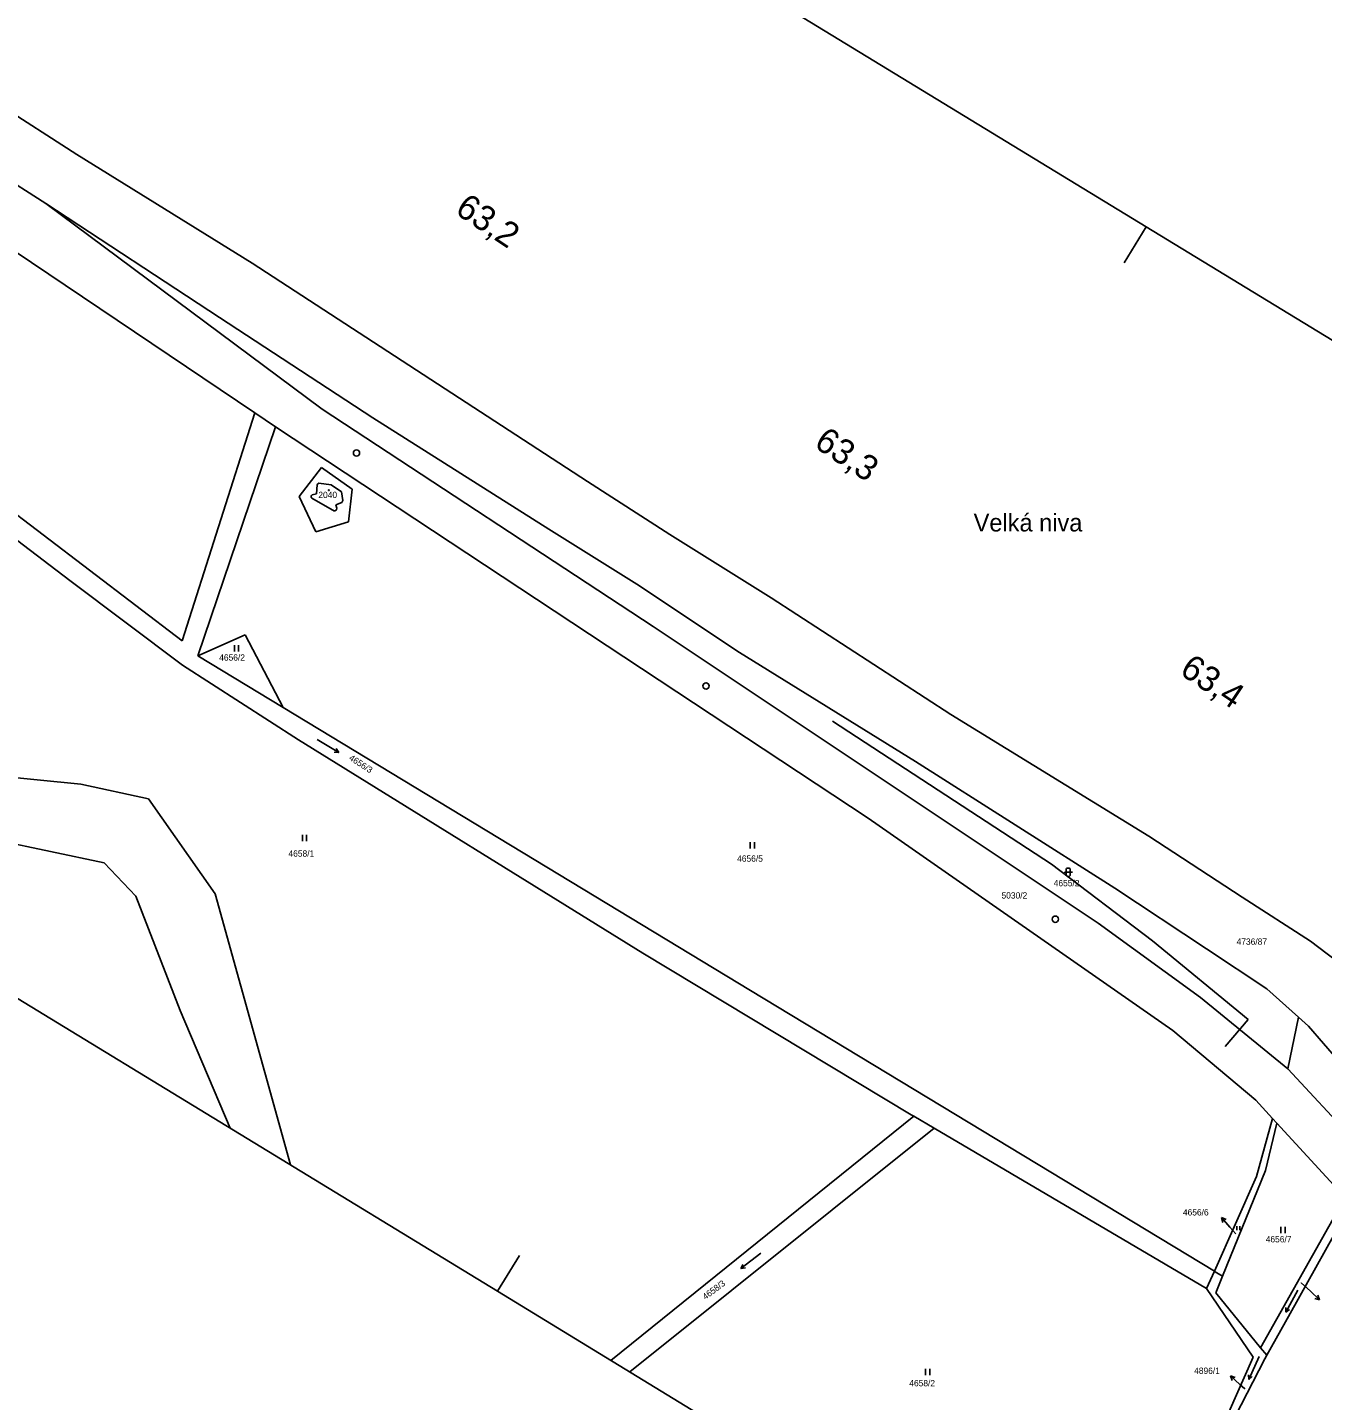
# Model space of a CAD drawing. Extents: x -804899 to -803847, y -1165742 to -1164942.
# Drawn here: x -804472.7 to -804164, y -1165549.5 to -1165222.3 of the extents above; entities that cross this region are included whole.
import ezdxf

# ---------------------------------------------------------------- set-up
doc = ezdxf.new("R2010")
doc.units = 0
for name, color, linetype in [('Default', 7, 'Continuous'), ('formát', 7, 'Continuous'), ('kilometráž - vrstava 7', 7, 'Continuous'), ('kn_celek - Cisla parcel pomocna', 7, 'Continuous'), ('kn_celek - Cisla pozemkovych parcel', 7, 'Continuous'), ('kn_celek - Cisla stavebnich parcel', 7, 'Continuous'), ('kn_celek - Dalsi prvky mapy popis', 7, 'Continuous'), ('kn_celek - Hranice parcel', 7, 'Continuous'), ('kn_celek - Vnitrni kresby', 7, 'Continuous'), ('kn_celek - Znacky budov', 7, 'Continuous'), ('kn_celek - Znacky kultur', 7, 'Continuous'), ('plochy - SZDC', 7, 'Continuous'), ('PSR_C2_3_trasa_Lenora - Kabelová trasa', 7, 'Continuous')]:
    doc.layers.add(name, color=color, linetype=linetype)

# ---------------------------------------------------------------- blocks, each defined once
blk = doc.blocks.new('316')
at = {"layer": 'Default'}
for p, q in [((-8.3, 10), (-10, 8.1)), ((-5, 10), (-8.3, 10)), ((-5, 15.5), (-5, 4.5)), ((-5, 10), (5, 10)), ((0.5, 20), (-0.5, 20)), ((-0.5, 0), (0.5, 0)), ((5, 4.5), (5, 15.5)), ((10, 10), (5, 10))]:
    blk.add_line(p, q, dxfattribs=at)
for centre, start, end in [((-0.5, 15.5), 90, 180), ((-0.5, 4.5), 180, 270), ((0.5, 15.5), 0, 90), ((0.5, 4.5), 270, 0)]:
    blk.add_arc(centre, 4.5, start, end, dxfattribs=at)
blk = doc.blocks.new('306')
at = {"layer": 'Default'}
for p, q in [((-5.2, 0), (-5.2, 15)), ((4.8, 0), (4.8, 15))]:
    blk.add_line(p, q, dxfattribs=at)
blk = doc.blocks.new('802')
at = {"layer": 'Default'}
for p, q in [((-30, 0), (30, 0)), ((20, 5), (30, 0)), ((30, 0), (20, -5))]:
    blk.add_line(p, q, dxfattribs=at)
blk = doc.blocks.new('402')
at = {"layer": 'Default'}
for p, q in [((-0.8, 0.8), (0.7, 0.8)), ((-0.8, 0.8), (-0.8, -0.7)), ((0.7, 0.8), (0.7, -0.7)), ((0.7, -0.7), (-0.8, -0.7))]:
    blk.add_line(p, q, dxfattribs=at)
blk = doc.blocks.new('Z61')
at = {"layer": 'Default'}
for p, q in [((0, 0), (30, 0)), ((30, 0), (19.2, 5.3)), ((30, 0), (19.2, -5.3))]:
    blk.add_line(p, q, dxfattribs=at)

msp = doc.modelspace()

# ---------------------------------------------------------------- linework, layer by layer
at = {"layer": 'formát'}
for p, q in [((-804206.05, -1165269.84), (-804743.98, -1164941.92)), ((-804360.64, -1165523.44), (-804898.57, -1165195.52)), ((-804206.05, -1165269.84), (-804211.25, -1165278.38)), ((-804026.74, -1165379.15), (-804206.05, -1165269.84)), ((-804355.43, -1165514.9), (-804360.64, -1165523.44)), ((-804181.33, -1165632.74), (-804360.64, -1165523.44))]:
    msp.add_line(p, q, dxfattribs=at)
at = {"layer": 'kilometráž - vrstava 7'}
for centre in [(-804394.24, -1165323.73), (-804310.94, -1165379.23), (-804227.7, -1165434.8)]:
    msp.add_circle(centre, 0.75, dxfattribs=at)
at = {"layer": 'kn_celek - Cisla parcel pomocna'}
for p, q in [((-804184.66, -1165509.79), (-804186.1, -1165508.15)), ((-804169.08, -1165521.47), (-804166.91, -1165523.46)), ((-804182.56, -1165546.73), (-804183.74, -1165545.65))]:
    msp.add_line(p, q, dxfattribs=at)
at = {"layer": 'kn_celek - Hranice parcel'}
for p, q in [((-804512.48, -1165219.51), (-804460.87, -1165252.62)), ((-804552.85, -1165223.84), (-804418.46, -1165314.18)), ((-804519.76, -1165231.32), (-804468.27, -1165264.32)), ((-804611.48, -1165241.21), (-804462.54, -1165354.11)), ((-804460.87, -1165252.62), (-804419.13, -1165278.5)), ((-804579.26, -1165259.3), (-804435.81, -1165368.47)), ((-804468.27, -1165264.32), (-804402.46, -1165313.29)), ((-804468.27, -1165264.32), (-804426.86, -1165291.43)), ((-804419.13, -1165278.5), (-804339.16, -1165330.48)), ((-804426.86, -1165291.43), (-804390.35, -1165315.35)), ((-804435.81, -1165368.47), (-804418.46, -1165314.18)), ((-804418.46, -1165314.18), (-804413.53, -1165317.49)), ((-804402.46, -1165313.29), (-804323.51, -1165365.07)), ((-804413.53, -1165317.49), (-804432.07, -1165372.08)), ((-804413.53, -1165317.49), (-804272.3, -1165410.7)), ((-804390.35, -1165315.35), (-804348.41, -1165341.86)), ((-804402.61, -1165327.22), (-804407.87, -1165334.06)), ((-804395.25, -1165332.31), (-804402.61, -1165327.22)), ((-804339.16, -1165330.48), (-804319.55, -1165343.18)), ((-804396.17, -1165340.16), (-804395.25, -1165332.31)), ((-804407.87, -1165334.06), (-804403.92, -1165342.5)), ((-804403.92, -1165342.5), (-804396.17, -1165340.16)), ((-804348.41, -1165341.86), (-804327.45, -1165354.94)), ((-804319.55, -1165343.18), (-804295.39, -1165358.24)), ((-804462.54, -1165354.11), (-804435.75, -1165374.24)), ((-804327.45, -1165354.94), (-804302.94, -1165371.26)), ((-804295.39, -1165358.24), (-804252.61, -1165386.06)), ((-804323.51, -1165365.07), (-804217.51, -1165435.77)), ((-804432.07, -1165372.08), (-804420.77, -1165367.05)), ((-804420.77, -1165367.05), (-804411.74, -1165384.38)), ((-804432.07, -1165372.08), (-804411.74, -1165384.38)), ((-804302.94, -1165371.26), (-804261.01, -1165397.26)), ((-804435.75, -1165374.24), (-804408.07, -1165392.08)), ((-804411.74, -1165384.38), (-804300.34, -1165451.78)), ((-804252.61, -1165386.06), (-804205.41, -1165415.05)), ((-804408.07, -1165392.08), (-804326.03, -1165442.88)), ((-804509.08, -1165397.79), (-804459.92, -1165402.62)), ((-804213.5, -1165427.44), (-804261.01, -1165397.26)), ((-804459.92, -1165402.62), (-804443.8, -1165406.13)), ((-804443.8, -1165406.13), (-804427.89, -1165428.73)), ((-804199.72, -1165461.33), (-804272.3, -1165410.7)), ((-804489.41, -1165414.02), (-804454.38, -1165421.34)), ((-804205.41, -1165415.05), (-804183.17, -1165429.52)), ((-804454.38, -1165421.34), (-804446.86, -1165429.35)), ((-804427.89, -1165428.73), (-804410, -1165493.35)), ((-804191.69, -1165441.88), (-804213.5, -1165427.44)), ((-804446.86, -1165429.35), (-804436.25, -1165456.55)), ((-804183.17, -1165429.52), (-804166.9, -1165440.05)), ((-804217.51, -1165435.77), (-804193.11, -1165453.43)), ((-804177.28, -1165451.4), (-804191.69, -1165441.88)), ((-804166.9, -1165440.05), (-804154.41, -1165449.48)), ((-804326.03, -1165442.88), (-804262.02, -1165481.4)), ((-804300.34, -1165451.78), (-804189.78, -1165518.67)), ((-804169.73, -1165458.18), (-804177.28, -1165451.4)), ((-804193.11, -1165453.43), (-804172.29, -1165470.42)), ((-804436.25, -1165456.55), (-804424.34, -1165484.6)), ((-804172.29, -1165470.42), (-804169.73, -1165458.18)), ((-804167.35, -1165460.31), (-804169.73, -1165458.18)), ((-804179.93, -1165477.89), (-804199.72, -1165461.33)), ((-804156, -1165473.46), (-804167.35, -1165460.31)), ((-804172.29, -1165470.42), (-804129.3, -1165516.81)), ((-804179.93, -1165477.89), (-804175.89, -1165482.28)), ((-804261.39, -1165481.77), (-804333.6, -1165539.92)), ((-804261.39, -1165481.77), (-804262.02, -1165481.4)), ((-804256.6, -1165484.59), (-804261.39, -1165481.77)), ((-804179.73, -1165496.08), (-804175.89, -1165482.28)), ((-804174.86, -1165483.4), (-804177.56, -1165494.7)), ((-804175.89, -1165482.28), (-804174.86, -1165483.4)), ((-804174.86, -1165483.4), (-804158.61, -1165501.07)), ((-804256.6, -1165484.59), (-804329.11, -1165542.66)), ((-804191.62, -1165522.81), (-804256.6, -1165484.59)), ((-804189.78, -1165518.67), (-804179.73, -1165496.08)), ((-804177.56, -1165494.7), (-804187.83, -1165519.85)), ((-804178.76, -1165536.91), (-804158.61, -1165501.07)), ((-804171.74, -1165528.78), (-804157.17, -1165502.7)), ((-804191.62, -1165522.81), (-804189.78, -1165518.67)), ((-804189.78, -1165518.67), (-804189.59, -1165518.78)), ((-804189.59, -1165518.78), (-804187.83, -1165519.85)), ((-804187.83, -1165519.85), (-804189.46, -1165523.84)), ((-804191.62, -1165522.81), (-804180.56, -1165539.16)), ((-804189.46, -1165523.84), (-804178.76, -1165536.91)), ((-804177.29, -1165538.71), (-804171.74, -1165528.78)), ((-804180.56, -1165539.16), (-804186.32, -1165552.24)), ((-804184.8, -1165553.3), (-804177.76, -1165539.56)), ((-804178.76, -1165536.91), (-804177.29, -1165538.71)), ((-804177.76, -1165539.56), (-804177.29, -1165538.71))]:
    msp.add_line(p, q, dxfattribs=at)
at = {"layer": 'kn_celek - Vnitrni kresby'}
for p, q in [((-804405.03, -1165334.04), (-804404.95, -1165333.84)), ((-804405.03, -1165334.34), (-804405.03, -1165334.04)), ((-804404.95, -1165333.84), (-804404.81, -1165333.67)), ((-804404.81, -1165333.67), (-804403.75, -1165333.45)), ((-804403.75, -1165333.45), (-804403.61, -1165331.31)), ((-804403.61, -1165331.31), (-804403.46, -1165331.1)), ((-804403.46, -1165331.1), (-804403.19, -1165330.9)), ((-804403.19, -1165330.9), (-804400.24, -1165331.34)), ((-804400.24, -1165331.34), (-804397.82, -1165332.97)), ((-804397.82, -1165332.97), (-804397.53, -1165335.03)), ((-804404.89, -1165334.45), (-804405.03, -1165334.34)), ((-804399.5, -1165337.55), (-804404.89, -1165334.45)), ((-804397.75, -1165335.5), (-804399.17, -1165336.08)), ((-804399.17, -1165336.08), (-804398.9, -1165336.87)), ((-804399.01, -1165337.18), (-804399.09, -1165337.37)), ((-804398.9, -1165336.87), (-804399.01, -1165337.18)), ((-804397.54, -1165335.23), (-804397.75, -1165335.5)), ((-804397.53, -1165335.03), (-804397.54, -1165335.23)), ((-804399.4, -1165337.54), (-804399.5, -1165337.55)), ((-804399.09, -1165337.37), (-804399.4, -1165337.54))]:
    msp.add_line(p, q, dxfattribs=at)
at = {"layer": 'plochy - SZDC'}
for p, q in [((-804552.85, -1165223.84), (-804418.46, -1165314.18)), ((-804468.27, -1165264.32), (-804519.76, -1165231.32)), ((-804426.86, -1165291.43), (-804468.27, -1165264.32)), ((-804468.27, -1165264.32), (-804402.46, -1165313.29)), ((-804402.46, -1165313.29), (-804468.27, -1165264.32)), ((-804390.35, -1165315.35), (-804426.86, -1165291.43)), ((-804418.46, -1165314.18), (-804413.53, -1165317.49)), ((-804402.46, -1165313.29), (-804323.51, -1165365.07)), ((-804323.51, -1165365.07), (-804402.46, -1165313.29)), ((-804413.53, -1165317.49), (-804272.3, -1165410.7)), ((-804348.41, -1165341.86), (-804390.35, -1165315.35)), ((-804327.45, -1165354.94), (-804348.41, -1165341.86)), ((-804302.94, -1165371.26), (-804327.45, -1165354.94)), ((-804323.51, -1165365.07), (-804217.51, -1165435.77)), ((-804217.51, -1165435.77), (-804323.51, -1165365.07)), ((-804261.01, -1165397.26), (-804302.94, -1165371.26)), ((-804213.5, -1165427.44), (-804261.01, -1165397.26)), ((-804272.3, -1165410.7), (-804199.72, -1165461.33)), ((-804191.69, -1165441.88), (-804213.5, -1165427.44)), ((-804217.51, -1165435.77), (-804193.11, -1165453.43)), ((-804193.11, -1165453.43), (-804217.51, -1165435.77)), ((-804177.28, -1165451.4), (-804191.69, -1165441.88)), ((-804169.73, -1165458.18), (-804177.28, -1165451.4)), ((-804193.11, -1165453.43), (-804172.29, -1165470.42)), ((-804172.29, -1165470.42), (-804193.11, -1165453.43)), ((-804172.29, -1165470.42), (-804169.73, -1165458.18)), ((-804199.72, -1165461.33), (-804179.93, -1165477.89)), ((-804129.3, -1165516.81), (-804172.29, -1165470.42)), ((-804179.93, -1165477.89), (-804175.89, -1165482.28)), ((-804175.89, -1165482.28), (-804174.86, -1165483.4)), ((-804174.86, -1165483.4), (-804158.61, -1165501.07))]:
    msp.add_line(p, q, dxfattribs=at)
at = {"layer": 'PSR_C2_3_trasa_Lenora - Kabelová trasa'}
msp.add_line((-804181.72, -1165458.66), (-804187.21, -1165465.17), dxfattribs=at)
msp.add_lwpolyline([(-804280.78, -1165387.58), (-804228.57, -1165421.69), (-804204.49, -1165439.97), (-804181.72, -1165458.66)], dxfattribs=at)

# ---------------------------------------------------------------- block references
at = {"layer": 'kn_celek - Cisla parcel pomocna', "xscale": 0.1, "yscale": 0.10000000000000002}
for p, rotation in [((-804186.1, -1165508.15), 131.16510000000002), ((-804166.91, -1165523.46), -42.54615000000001), ((-804183.74, -1165545.65), 137.64257999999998)]:
    msp.add_blockref('Z61', p, dxfattribs=dict(at, rotation=rotation))
at = {"layer": 'kn_celek - Znacky budov', "xscale": 0.1, "yscale": 0.10000000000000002}
msp.add_blockref('402', (-804400.86, -1165332.56), dxfattribs=at)
at = {"layer": 'kn_celek - Znacky kultur'}
for name, p, xscale, yscale in [('306', (-804422.82, -1165370.99), 0.1, 0.10000000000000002), ('306', (-804406.62, -1165416.24), 0.1, 0.10000000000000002), ('306', (-804299.86, -1165417.93), 0.1, 0.10000000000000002), ('316', (-804224.62, -1165424.63), 0.1, 0.10000000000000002), ('306', (-804184.05, -1165508.93), 0.067, 0.067), ('306', (-804173.4, -1165509.61), 0.1, 0.10000000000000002), ('306', (-804258.11, -1165543.41), 0.1, 0.10000000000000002)]:
    msp.add_blockref(name, p, dxfattribs=dict(at, xscale=xscale, yscale=yscale))
for p, xscale, yscale, rotation in [((-804401.03, -1165393.52), 0.1, 0.10000000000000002, -31.53986999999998), ((-804300.28, -1165516.23), 0.1, 0.09999999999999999, -142.49439), ((-804171.33, -1165525.83), 0.10000000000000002, 0.1, -118.66841999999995), ((-804180.37, -1165541.74), 0.10000000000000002, 0.1, -114.27461999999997)]:
    msp.add_blockref('802', p, dxfattribs=dict(at, xscale=xscale, yscale=yscale, rotation=rotation))

# ---------------------------------------------------------------- texts
at = {"layer": 'kilometráž - vrstava 7'}
for s, rotation, p in [('63,2', 326.3093, (-804371.02, -1165266.51)), ('63,3', 326.3024, (-804285.46, -1165322.14)), ('63,4', 326.2162, (-804198.33, -1165376.26))]:
    msp.add_text(s, height=6, rotation=rotation, dxfattribs=at).set_placement(p)
at = {"layer": 'kn_celek - Cisla parcel pomocna'}
for s, p in [('4656/6', (-804197.28, -1165505.39)), ('4896/1', (-804194.6, -1165543.13))]:
    msp.add_text(s, height=1.5, dxfattribs=at).set_placement(p)
at = {"layer": 'kn_celek - Cisla pozemkovych parcel'}
for s, height, p in [('4656/2', 1.5, (-804426.96, -1165373.19)), ('4658/1', 1.5, (-804410.45, -1165419.9)), ('4656/5', 1.5, (-804303.52, -1165421.1)), ('4655/2', 1.5, (-804228.07, -1165426.95)), ('5030/2', 1.5, (-804240.51, -1165429.88)), ('4736/87', 1.5, (-804184.48, -1165440.89)), ('4656/6', 0.1, (-804184.93, -1165509.76)), ('4656/7', 1.5, (-804177.54, -1165511.81)), ('4896/2', 0.1, (-804169.36, -1165521.44)), ('4658/2', 1.5, (-804262.49, -1165546.09)), ('4896/1', 0.1, (-804182.81, -1165546.7))]:
    msp.add_text(s, height=height, dxfattribs=at).set_placement(p)
for s, rotation, p in [('4656/3', 326.8787, (-804396.17, -1165396.73)), ('4658/3', 36.937, (-804311.1, -1165525.56))]:
    msp.add_text(s, height=1.5, rotation=rotation, dxfattribs=at).set_placement(p)
at = {"layer": 'kn_celek - Cisla stavebnich parcel'}
msp.add_text('2040', height=1.5, dxfattribs=at).set_placement((-804403.33, -1165334.46))
at = {"layer": 'kn_celek - Dalsi prvky mapy popis'}
msp.add_text('Velká niva', height=4.2, dxfattribs=at).set_placement((-804247.15, -1165342.42))

doc.saveas('drawing.dxf')
